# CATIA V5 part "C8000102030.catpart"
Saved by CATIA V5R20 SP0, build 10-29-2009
Part number: C8000102030
Source: Unknown
Property "A": "30"
Property "ARTICLENO": "C8000102030"
Property "B": "13"
Property "BOMINFO": "C8000102030"
Property "C": "46"
Property "CA": "C8000102030"
Property "D1": "38"
Property "DES": "ROTATING EYEBOLT WITH RING Ton 1,12 M20x30"
Property "E": "50"
Property "H": "105"
Property "L": "30"
Property "LINA": "C8000102030"
Property "NB": "C8000102030"
Property "NBSYN": "$CODE."
Property "NN": "C800"
Property "NT": "Rotating eyebolt with ring"
Property "SIZE": "M20"
Property "SUPPLIER": "CF"
Property "SW": "30"
Property "WEIGHT": "530"
Property "WLL": "1.12"
Bounding box of the stored display mesh (mm): x -27.837 to 28, y -30 to 117.837, z -19 to 19
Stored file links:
  C:\Users\Utente\Desktop\3D files 800\C8000102030.catpart
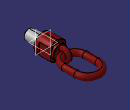
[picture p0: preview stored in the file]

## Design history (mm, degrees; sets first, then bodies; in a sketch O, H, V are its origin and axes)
Body1 "Geometry.1" (main body)
  Solid1 "C8000102030.catpart": solid without history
